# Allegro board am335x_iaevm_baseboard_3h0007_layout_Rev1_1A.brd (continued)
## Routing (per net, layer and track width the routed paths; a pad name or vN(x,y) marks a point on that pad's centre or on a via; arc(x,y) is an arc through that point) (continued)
GND_OSC0: length 14.5
  TOP w0.254: U2.V11 92.88,86.2 93.53,86.85 94.23,86.85 95.19,85.89 98.58,85.89 100.29,84.19 v1(100.29,83.02) ; C4.2 102.02,81.19 101.64,81.57 v1(101.64,81.83) 101.64,82.08 C5.2
  BOTTOM w0.254: v1(101.64,81.83) 101.13,82.33 101,82.33 C67.2 100.62,82.71 100.6,82.71 v1(100.29,83.02)
GND_OSC1: length 13.8
  TOP w0.102: U2.A5 77.94,81.14 77.1,81.14
  TOP w0.121: 77.1,81.14 76.22,81.14 75.24,80.16 71.56,80.16 71.31,79.92 67.56,79.92 C2.1 C3.1
GNDA_ADC: length 45.1
  TOP w0.305: v2(81,83.4) U2.E8
  TOP w0.508: v1(49.44,75.73) v1(57.19,75.73) ; v1(58.9,84.75) 59.66,84.75 59.92,84.49 v1(64.27,84.49) 64.53,84.75 R45.1
  BOTTOM w0.127: 79.56,82.99 79.79,83.22 79.79,83.6 80.05,83.86 80.54,83.86 v2(81,83.4)
  BOTTOM w0.152: 79.56,82.99 79.13,82.99 79.03,83.1 77.15,83.1
  BOTTOM w0.508: 77.15,83.1 76.94,83.1 75.99,82.14 FB10.1 75.09,83.25 73.9,84.44 71.16,84.44 70.66,84.94 66.83,84.94 66.38,84.49 v1(64.27,84.49) ; v1(57.19,75.73) 57.19,79.03 58.88,80.73 58.88,81.93 58.89,81.93 58.89,84.73 v1(58.9,84.75) ; C63.2 v1(49.44,75.73)
GNDA_TSC: length 60.2
  TOP w0.508: v1(43.29,80.4) 54.55,80.4 57.87,83.73 R45.2 65.19,83.48 R51.2 C13.2 C14.2 C11.2 C12.2 ; 49.82,57.31 J9.11
  BOTTOM w0.508: 49.82,57.31 50.96,57.31 51.45,57.8 51.45,64.45 49.62,66.28 47.76,66.28 42.18,71.87 42.18,79.29 v1(43.29,80.4)
GNDUSB0: length 26
  TOP w0.635: v1(124.62,168.26) 124.91,168.55 J14.S4 126.62,166.82 126.87,166.57 126.87,166 J14.S2 ; J14.S1 134.08,166 134.82,166.74 J14.S3 136.66,168.55 v1(136.94,168.26) FB14.2
  BOTTOM w0.635: v1(124.62,168.26) v1(136.94,168.26)
GNDUSB1: length 16.7
  TOP w0.635: FB19.2 154.6,165.66 J18.S1
  BOTTOM w0.635: J18.S1 151.94,168.31 139.98,168.31 J18.S2
V1_8D: length 35.1
  TOP w0.508: C133.1 v1(135.8,128.46) ; v1(133.01,50.52) 130.53,50.52 128.37,48.36 116.31,48.36 114.96,47.02 v1(113.56,47.02)
  LY4 w0.483: 132.75,87.13 J8.2 133.56,86.52
  LY4 w0.514: 135.8,123.46 J3.1 ; J3.1 134.89,124.37 ; J3.1 136.71,124.37 ; J3.1 135.8,125.28
  BOTTOM w0.508: C261.1 113.57,47.01 v1(113.56,47.02) R472.1 ; J8.2 132.63,86.65 C138.1 ; J3.1 v1(135.8,128.46)
V3_3D: length 210
  TOP w0.254: U32.6 v1(66.86,33.53)
  TOP w0.381: C140.1 50.08,65.7 49.82,65.44 49.82,63.66
  TOP w0.508: v1(75.09,146.34) 92.11,146.34 93.2,147.43 111.64,147.43 114.74,150.53 116.05,150.53 123.19,143.39 128.71,143.39 129.96,142.15 135.95,142.15 137.22,140.88 155.99,140.88 156.88,141.77 R386.2 ; v1(66.86,33.53) 66.86,32.84 67.09,32.61 C222.1
  TOP w0.635: v1(73.57,39.15) v1(71.03,39.15) v1(65.95,39.15) 58.97,39.15 58.52,38.7 ; 58.52,38.7 v1(46.97,38.7) ; 58.52,38.7 58.52,35.73 R544.2 58.77,33.69 59.62,32.84 66.86,32.84 ; v1(64.3,45.88) 63.09,44.68 59.03,44.68 57.82,45.88 50.33,45.88 v1(48.3,47.92)
  LY4 w0.514: 50.63,63.66 49.82,63.66 49.82,64.27 ; 48.17,136.16 J5.39 ; J5.39 49.08,137.07 ; J5.39 48.17,137.98 ; J5.39 47.26,137.07 ; 68.85,125.64 J6.15 ; J6.15 69.76,124.73 ; J6.15 70.67,125.64 ; J6.15 69.76,126.55
  BOTTOM w0.254: U27.6 65.59,46.03 C215.1
  BOTTOM w0.508: C135.1 v1(48.93,135.29) ; C134.1 69.76,124.24 J6.15
  BOTTOM w0.635: v1(46.97,38.7) v1(46.97,47.86) ; R454.2 v1(71.03,39.15) ; 73.57,40.42 v1(73.57,39.15) ; R455.2 v1(65.95,39.15) ; C215.1 v1(64.3,45.88)
  BOTTOM w0.762: R68.1 105.75,41.64 105.75,28.41 102.91,25.56 v1(102.91,22.26)
  vias: v1(113.45,24.55) v1(113.45,23.66) v1(113.45,22.77)
V5_0D: length 38.7
  TOP w0.121: U24.E2 U24.E1
  TOP w0.381: J7.2 J7.1
  TOP w0.508: v1(132.63,126.78) C132.1
  TOP w0.635: 136.05,146.79 U22.3 ; 136.05,146.79 134.78,146.79 U22.2 ; 136.05,146.79 143.1,146.79 ; C270.1 148.64,146.79 144.37,146.79 ; 143.1,146.79 U29.2 ; 143.1,146.79 144.37,146.79 ; 144.37,146.79 U29.3
  TOP w0.762: C137.1 139.23,88.05 137.71,86.52 J7.2
  LY4 w0.483: 135.93,87.13 J7.1 135.11,86.52 ; 138.01,86.52 J7.2 137.2,87.13
  LY4 w0.514: J3.2 133.26,125.28 ; J3.2 133.26,123.46 ; J3.2 132.35,124.37
  BOTTOM w0.381: 148.12,147.1 148.37,147.1
  BOTTOM w0.508: v1(132.63,126.78) 133.26,126.15 J3.2 ; 148.37,147.1 v1(149.52,148.25)
  BOTTOM w0.762: J7.1 134.66,86.52 C136.1
V5_0D_EN: length 1.6
  TOP w0.121: U24.A4 156.79,144.78 R386.1
VBAT: length 147.3
  TOP w0.121: U24.A1 U24.A2
  TOP w0.203: U4.6 89.25,29.68 89.16,29.6 v1(89.16,29.4) ; 93,31.49 U4.13 ; U4.3 88.05,30.18 88.02,30.15 88.02,29.85 87.67,29.5 v1(87.67,29.48) ; v1(90.53,37.63) 90.45,37.55 U4.28 ; v1(93.33,36) 93.07,35.75 93.07,35.7 92.87,35.49 U4.23 ; U4.36 87.25,37.01 87.11,37.15 ; U4.47 85.87,31.89 85.67,31.7 85.67,31.44 ; 85.51,34.29 U4.41
  TOP w0.381: v1(85.25,30.01) 85.25,30.02 85.25,31.03 85.67,31.44 ; R239.2 v1(126.91,79.79) ; v1(85.29,34.29) 85.51,34.29 ; 87.11,37.15 86.97,37.29 86.97,37.57 v1(86.91,37.63) ; v1(93.61,31.15) 93.34,31.15 93,31.49
  TOP w0.502: 77.23,10.2 SW1.2 ; SW1.2 79.06,10.2 ; SW1.2 78.14,11.11 ; SW1.2 78.14,9.28 ; 88.81,19.32 TP25.1 ; TP25.1 87.77,20.36 ; TP25.1 89.85,20.36 ; TP25.1 88.81,21.4
  TOP w0.762: J8.1 130.34,86.52 129.96,86.14 129.96,86.11 129.61,85.76 C139.1
  LY3 w1.016: v1(63.54,123.23) 34.45,123.23 33.95,122.72 v1(31.91,122.72)
  LY4 w0.483: 130.67,86.52 J8.1 131.48,87.13
  LY4 w0.514: 87.77,20.36 TP25.1 ; TP25.1 88.81,21.4 ; TP25.1 89.85,20.36 ; TP25.1 88.81,19.32 ; J19.2 124.65,59.92 ; J19.2 123.74,59 ; J19.2 122.82,59.92 ; J19.2 123.74,60.83 ; 77.23,10.2 SW1.2 ; SW1.2 78.14,9.28 ; SW1.2 78.14,11.11 ; SW1.2 79.06,10.2 ; J19.1 124.65,62.46 ; J19.1 123.74,61.54 ; J19.1 122.82,62.46 ; J19.1 123.74,63.37
  BOTTOM w0.381: C141.1 64.14,124.15 64.14,124.68
  BOTTOM w0.762: R80.2 6.26,87.41 6.39,87.29 ; R81.2 6.77,83.1 ; R82.2 6.77,78.65 ; R83.2 6.45,74.33
  BOTTOM w1.016: C253.1 v1(86.91,37.63) 86.91,37.76 86.38,38.28 C238.1 ; C240.1 92.38,31.15 v1(93.61,31.15) ; 6.45,74.33 6.77,74.65 6.77,86.91 6.39,87.29 6.39,95.03 11.85,100.49 v1(14.52,100.49) ; C252.1 88.72,30.32 89.16,29.88 v1(89.16,29.4) ; v1(31.91,101.51) v1(31.91,122.72) ; v1(93.33,36) 94.77,36 C251.1 ; C254.1 87.54,30.43 87.54,29.6 v1(87.67,29.48) ; C236.1 84.72,27.72 85.64,28.64 85.64,29.63 85.26,30.01 85.25,30.01 v1(85.25,30.01) ; C250.1 90.53,36.63 v1(90.53,37.63) ; J6.19 64.14,125.1 64.14,124.68 63.54,124.08 v1(63.54,123.23)
  vias: v1(83.48,20.36) v1(84.75,20.36) v1(85.76,20.36) v1(157.77,148.5) v1(158.53,148.5)
VBUS0_OTG_CAP: length 3.7
  TOP w0.635: J36.2 131.99,153.9 C182.1
VBUS1_OTG_CAP: length 6.6
  TOP w0.502: J37.2 154.53,158.75 ; J37.2 153.49,157.71 ; J37.2 154.53,156.67
  TOP w0.635: C185.1 J37.2
VDD1_SMPS: length 25.5
  TOP w0.254: U32.8 v1(67.79,35.15)
  TOP w0.635: R46.1 73.68,36.85 74.12,36.4 v1(74.91,36.4) ; v1(71.79,45.38) v1(71.79,44.74) 73.1,44.74 73.36,45 v1(75.54,45) 80.68,45
  LY3 w0.514: J19.6 124.65,49.76 ; J19.6 123.74,50.67 ; J19.6 123.74,48.84 ; J19.6 122.82,49.76
  BOTTOM w0.635: v1(74.91,36.4) 74.91,44.36 v1(75.54,45)
  vias: v1(81.06,45.38) v1(81.44,46.01) v1(81.83,45.38)
VDD2_SMPS: length 94.3
  BOTTOM w0.254: v1(70.01,46.93) 69.51,46.93 69.4,47.03 U27.8
  BOTTOM w1.016: J19.7 122.85,46.33 122.85,46.25 121.45,44.85 121.45,40.11 119.04,37.69 119.04,32.93 118.66,32.55 118.66,20.48 117.39,19.21 107.99,19.21 107.48,18.71 94.59,18.71 93.57,17.69 93.31,17.69 87.46,17.69 86.99,18.16 81.42,18.16 75.54,24.04 75.54,34.07 77.76,36.3 v1(77.76,38.26)
  vias: v1(70.52,48.42) v1(70.52,47.66) v1(76.62,38.26)
VDD3_SMPS: length 35.1
  TOP w0.508: v1(91.35,45.88) 92,45.88 R470.1 92.23,45.12 v1(91.35,45.12)
  TOP w0.635: J19.8 122.75,43.69 109.99,43.69 108.11,45.57 97.32,45.57 97.13,45.38 92.5,45.38 R470.1
VDD_CORE: length 62.6
  TOP w0.305: U2.J12 v2(84.2,87.4)
  TOP w0.381: U2.F6 v2(82.6,81.8) U2.G6 ; U2.L6 v2(85.8,81.8) U2.K6 ; v2(86.6,82.6) U2.L7 ; U2.N13 v2(87.4,88.2) U2.M13 ; v2(82.6,85.8) U2.G10 ; U2.N9 v2(88.2,84.2) U2.N8 ; U2.F7 v2(82.6,82.6) U2.G7 ; v2(86.6,83.4) U2.L8 v2(85.8,83.4) U2.K8 ; v2(87.4,86.6) U2.M11 ; v2(86.6,84.2) U2.L9 ; v2(88.2,87.4) U2.N12 ; U2.H11 v2(83.4,86.6) ; v2(85.8,87.4) U2.K12
  TOP w0.635: C17.1 v1(67.35,73.7)
  TOP w1.016: v1(67.35,73.7) v1(66.9,73.25) v1(66.46,72.81) 65.35,71.7 65.35,71.03 ; R32.2 70.54,45.78 71.16,46.39 73.32,46.39 ; C232.1 65.35,71.03 ; 65.35,71.03 65.19,70.86 65.19,69.86 62.01,66.69 62.01,61.24 64.99,58.26 65.26,58.26 v1(65.89,57.63) v1(66.46,57.06) v1(66.46,56.43)
  BOTTOM w0.381: v2(86.6,84.2) 86.14,84.66 C35.1 ; v2(82.6,85.8) 82.6,85.37 C19.1 ; C36.1 88.05,84.35 v2(88.2,84.2) ; v2(85.8,83.4) 85.65,83.4 85.19,83.86 C24.1 ; C34.1 85.5,87.1 v2(85.8,87.4)
  BOTTOM w0.635: 66.2,77 v1(65.06,77) ; C23.1 v1(70.14,72.94)
  BOTTOM w1.016: v1(65.89,57.63) v1(66.46,57.06) v1(66.46,56.43) 67.09,55.8 67.09,52.37 69.95,49.5 71.99,49.5 72.31,49.19 73.7,49.19 74.97,47.92 v1(74.97,46.65)
  vias: v1(73.57,46.65) v1(74.33,46.01)
VDD_MPU: length 77.9
  TOP w0.381: U2.F10 v2(81.8,85.8) U2.F11 U2.F12 v2(81.8,87.4) U2.F13 v2(82.6,88.2) U2.G13 83.06,87.8 83.18,87.92 83.62,87.92 83.74,87.8 U2.H13 v2(84.2,88.2) U2.J13
  TOP w0.635: v1(73.95,34.81) 73.85,34.71 73.19,34.71 72.68,34.2 R46.2
  LY3 w1.016: 64.93,81.83 64.92,81.81 61.64,81.81 60.92,81.09 60.92,80.02 63.49,77.46 63.49,69.86 64.86,68.49 65.44,68.49 66.2,67.73 v1(66.2,66.59) v1(66.2,65.95) v1(66.2,65.32)
  LY4 w1.016: v1(73.98,33.26) v1(73.98,34.05) 73.95,34.07 v1(73.95,34.81) 73.95,36.87 75.09,38.01 75.09,42.96 76.43,44.3 76.43,46.71 74.46,48.68 74.46,51.6 72.94,53.12 69.13,53.12 67.7,54.55 67.7,58.49 67.25,58.94 67.25,63.38 66.2,64.43 v1(66.2,65.32) v1(66.2,65.95) v1(66.2,66.59)
  BOTTOM w0.381: C83.1 84.42,87.98 v2(84.2,88.2) ; v2(81.8,87.4) 81.8,86.69 C41.1 ; v2(81.8,85.8) 81.8,85.15 C53.1
  BOTTOM w0.635: 69.38,81.7 70.01,82.33 v1(70.52,82.33) ; C56.1 71.41,81.57 v1(71.67,81.83) ; v1(65.32,80.81) 65.44,80.94 66.19,80.94 C246.1
VDD_RTC: length 6
  TOP w0.381: v2(80.2,81.8) U2.D6
  BOTTOM w0.203: 79.03,82.27 79.54,82.27 79.58,82.23 79.58,82.23 79.83,81.98 79.83,81.98 80.01,81.8 v2(80.2,81.8)
  BOTTOM w0.508: C65.1 76.58,80.81 76.89,81.13 76.91,81.13 78.05,82.27 79.03,82.27
VDDA1P8V_USB0: length 80
  TOP w0.381: v2(89.8,90.6) U2.R16 ; v2(88.2,90.6) U2.N16
  TOP w0.508: v1(95.54,131.89) 97.42,131.89 98.16,132.63 v1(116.62,132.63) ; C61.1 v1(115.86,136.94) 115.86,138.53 114.72,139.67 114.72,141.1 R502.2
  LY4 w0.381: v2(89.8,90.6) 89.24,91.16 88.75,91.16 88.2,90.61 v2(88.2,90.6)
  BOTTOM w0.508: v1(116.62,132.63) 116.62,136.18 v1(115.86,136.94) ; v1(95.54,131.89) 95.54,116.62 96.05,116.12 96.05,112.43 94.78,111.16 94.78,106.59 95.52,105.85 95.52,101.97 92.67,99.12 92.67,98.29 89.19,94.81 89.19,91.73 88.49,91.03 88.49,90.89 v2(88.2,90.6)
VDDA3P3V_USB0: length 76.1
  TOP w0.381: v2(89.8,89.8) U2.R15 ; v2(88.2,89.8) U2.N15
  TOP w0.508: R504.2 107.58,139.89 109.58,137.89 109.58,137.82 ; v1(108.88,104.66) 107.94,103.72 95.46,103.72 94.32,102.57 94.32,98.52 92.87,97.08 v1(92.87,96.56) ; 109.58,137.82 109.58,136.88 C62.1 ; 109.58,137.82 v1(109.59,137.81)
  LY3 w0.102: 91.2,91.48 91.32,91.35 ; v2(89.8,89.8) 89.79,89.8
  LY3 w0.127: 90.19,90.19 90.92,90.19 91.05,90.32 91.05,91.2 91.04,91.2 90.32,91.2 90.19,91.07 90.19,90.19 ; 90.19,90.19 90.18,90.18
  LY3 w0.254: 90.18,90.18 v2(89.8,89.8)
  LY3 w0.508: 91.05,91.2 91.2,91.35 91.2,94.98 92.78,96.56 v1(92.87,96.56)
  BOTTOM w0.102: 88.2,89.8 v2(88.2,89.8) 88.58,90.18 89.42,90.18 v2(89.8,89.8) 89.58,89.58 89.39,89.58 89.19,89.38 88.62,89.38 88.2,89.8
  BOTTOM w0.508: v1(108.88,104.66) 108.88,137.1 v1(109.59,137.81)
VDDA_ADC: length 157.6
  TOP w0.121: 124.62,160.69 124.62,160.69 124.74,160.57 124.75,160.57
  TOP w0.508: R30.1 65.64,88.5 65.64,88.34 65.63,88.34 v1(65.63,86.91) 65.32,86.59 58.07,86.59 v1(58.01,86.65) ; v1(53.76,78.78) 48.3,78.78 v1(47.92,78.4) ; Q5.S 125.82,160.01 R565.2 124.75,160.57 v1(124.37,160.95)
  LY3 w0.508: v1(112.25,108.85) 108.9,112.2 98.59,112.2 98.26,111.88 91.12,111.88 89.79,110.55 77.89,110.55 77.45,110.12 76.14,110.12 v1(73.49,107.48)
  LY4 w0.508: v1(65.63,86.91) 65.67,86.91 68.11,89.34 70.32,89.34 71.41,90.44 71.41,93.14 72.81,94.53 72.81,106.79 v1(73.49,107.48)
  BOTTOM w0.508: v1(58.01,86.65) 58.01,85.93 58.25,85.69 58.25,82.2 58.25,82.19 58.25,81.11 55.92,78.78 v1(53.76,78.78) 53.7,78.72 FB9.1 ; v1(124.37,160.95) 123.1,159.68 123.1,156.5 122.08,155.49 122.08,146.6 120.79,145.3 120.79,135.89 115.56,130.66 115.56,128.51 114.03,126.99 114.03,125.69 112.25,123.91 v1(112.25,108.85) ; v1(47.92,78.4) R501.2
VDDMPU_MON: length 4.8
  TOP w0.381: U2.A2 77.48,79 76.87,78.4 73.82,78.4 R561.1
VDDS_DDR: length 94.4
  TOP w0.305: v1(95.8,67.79) 95.22,67.22 95.03,67.22
  TOP w0.381: v1(97.96,56.64) U31.C9 ; v1(75.74,63.84) U8.C1 ; v1(73.34,63.84) U8.E1 ; v1(97.96,63.84) U31.C1 ; U8.C7 75.67,58.3 75.67,58.27 v1(75.73,58.2) ; v1(73.34,56.64) U8.E9 ; v1(75.74,56.64) U8.C9 ; v1(97.96,61.44) U31.C3 ; v1(99.56,56.64) U31.A9 ; v1(70.94,56.64) U8.H9 ; v1(77.33,63.84) U8.A1 ; v1(95.56,63.84) U31.E1 ; v1(93.16,56.64) U31.H9 ; v1(77.33,56.64) U8.A9 ; v1(90.76,63.84) U31.L1 ; v1(68.54,63.84) U8.L1 ; v1(95.56,56.64) U31.E9 ; v1(99.56,63.84) U31.A1 ; v1(75.74,61.44) U8.C3 ; v1(97.96,58.24) U31.C7
  TOP w0.508: v1(67.6,68.62) 67.6,69.51 67.86,69.76 C266.1 68.76,68.7 v1(68.62,68.55)
  TOP w0.635: R508.1 107.61,69.44 107.35,69.19 v1(105.6,69.19) v1(104.76,69.19) ; v1(103.8,38.96) 120.56,38.96 J19.9 ; R467.1 103.8,28.37 v1(103.8,29.37) v1(103.8,30.64)
  BOTTOM w0.254: v1(77.33,56.64) 76.87,56.17 C155.1 ; v1(97.96,58.24) 97.83,58.37 C195.1
  BOTTOM w0.305: C125.1 69,68.17 v1(68.62,68.55)
  BOTTOM w0.381: v1(73.34,56.64) 73.13,56.43 C126.1 ; 70.9,55.79 70.94,55.82 v1(70.94,56.64) ; C218.1 68.62,63.92 v1(68.54,63.84) ; v1(90.76,63.84) 90.84,63.92 C188.1 ; v1(93.16,56.64) 93.16,55.82 C174.1 ; C221.1 75.6,61.3 v1(75.74,61.44) ; C216.1 99.48,63.92 v1(99.56,63.84) ; v1(95.56,63.84) 95.65,63.84 96.3,64.49 C202.1 ; v1(99.56,56.64) 99.73,56.46 C181.1 ; C156.1 97.83,61.3 v1(97.96,61.44) ; C266.1 v1(67.6,68.62) ; v1(73.34,63.84) 73.55,63.84 74.08,64.36 C219.1 ; C217.1 77.25,63.92 v1(77.33,63.84) ; v1(97.57,54.8) C189.1 97.95,56.17 97.95,56.63 v1(97.96,56.64)
  BOTTOM w0.635: v1(99.1,55.03) v1(99.73,55.03) 99.73,50.9 98.4,49.57 98.4,47.28 103.8,41.88 v1(103.8,38.96) v1(103.8,30.64) v1(103.8,29.37)
VDDS_OSC: length 47.5
  TOP w0.305: U2.R11 v2(89.8,86.6)
  LY4 w0.508: v1(93.79,85.53) 93.51,85.25 93.51,84 94.66,82.84 96.17,82.84 97.31,83.98 100.49,83.98 101,83.48 101,81.44 101.38,81.06 v1(102.97,81.06)
  BOTTOM w0.381: v2(89.8,86.6) 90.87,85.53 v1(93.79,85.53)
  BOTTOM w0.508: R506.1 113.54,65 110.72,65 109.83,65.89 109.83,77.57 106.34,81.06 v1(102.97,81.06) 101.26,81.06 C67.1
VDDS_PLL_CORE_LCD: length 36.1
  TOP w0.102: U2.R10 89.41,85.4
  TOP w0.381: 89.41,85.4 v2(89.8,85.01)
  LY4 w0.508: v1(99.35,81.89) 98.26,81.89 97.94,82.21 94.4,82.21 91.02,85.58 90.36,85.58 90.02,85.24 90.02,85.23 v2(89.8,85.01)
  BOTTOM w0.508: v1(99.35,81.89) 99.67,81.57 99.68,81.57 100.05,81.2 100.05,81.13 100.75,80.43 105.45,80.43 107.51,78.37 107.51,66.42 107.48,66.39 C64.1 107.51,65.67 R503.1
VDDS_PLL_DDR: length 44.2
  TOP w0.381: U2.E7 v2(81,82.6)
  LY3 w0.102: v2(81,82.6) 80.99,82.6 80.61,82.98 79.93,82.98 79.54,82.59 79.92,82.21 80.62,82.21 81,82.59 v2(81,82.6)
  LY3 w0.508: 79.54,82.59 78.65,82.59 75.41,79.35 68.81,79.35 v1(68.24,78.78)
  BOTTOM w0.508: v1(68.24,78.78) 68.24,75.08 68.3,75.02 68.3,73.12 65.7,70.52 65.7,69.51 62.9,66.71 C73.1 62.9,59.16 59.95,56.2 R507.2
VDDS_PLL_MPU: length 46.8
  TOP w0.102: U2.H15 v2(83.4,89.8)
  TOP w0.508: R497.2 94.24,115.86 v1(94.24,117)
  LY3 w0.508: v1(81.93,111.39) 89.73,111.39 91.03,112.69 v1(94.27,112.69)
  LY4 w0.102: 82.18,90.21 82.18,89.6 82.4,89.38 82.97,89.38 83.39,89.8 v2(83.4,89.8) 83.4,89.84 83,90.24 ; 82.18,90.21 82.18,90.72 82.49,91.03 83,91.03 83,90.24 ; 82.18,90.21 82.97,90.21 83,90.24
  LY4 w0.508: v1(81.93,111.39) 81.44,110.91 81.44,104.81 80.96,104.32 80.96,100 81.28,99.68 81.28,98.49 80.85,98.06 80.85,93.71 83,91.56 83,91.03
  BOTTOM w0.508: v1(94.27,112.69) C70.1 94.27,114.34 94.24,114.37 v1(94.24,117)
VDDS_RTC: length 37.2
  TOP w0.305: v2(80.2,82.6) U2.D7
  BOTTOM w0.508: v1(70.52,81.5) 70.07,81.05 70.07,80.74 68.94,79.61 68.94,72.62 66.33,70.01 66.33,68.24 65.12,67.03 C66.1 64.43,58.58 64.43,57.06 64.94,56.55 64.94,52.43 64.68,52.17 64.68,50.14 63.85,49.31 R505.1
VDDS_SRAM_CORE_BG: length 49.3
  TOP w0.381: v2(81,84.2) U2.E9
  TOP w0.508: v1(50.2,102.53) 50.33,102.65 66.51,102.65 v1(66.56,102.7)
  BOTTOM w0.102: 78.84,84.62 79.86,84.62 80.28,84.2 v2(81,84.2)
  BOTTOM w0.508: R500.2 49.11,102.75 49.97,102.75 v1(50.2,102.53) 50.33,102.4 51.09,102.4 ; v1(66.56,102.7) 66.56,93.59 67.18,92.96 67.18,90.23 68.92,88.5 71.26,88.5 72.05,87.71 72.05,87.16 73.51,85.7 74.53,85.7 75.86,84.37 78.59,84.37 78.84,84.62
VDDS_SRAM_MPU_BB: length 60.8
  TOP w0.381: v2(80.2,85.8) U2.D10
  TOP w0.508: v1(51.93,107.4) 57.97,107.4 58.84,106.54 66.36,106.54 v1(67.22,107.4)
  BOTTOM w0.381: 79.59,86.38 79.96,86.02 79.98,86.02 v2(80.2,85.8)
  BOTTOM w0.508: v1(51.93,107.4) 51.93,98.92 C69.1 ; 79.59,86.38 77.41,86.38 76.82,86.97 74.56,86.97 74.56,86.97 74.03,86.97 74.03,86.97 73.25,86.97 72.68,87.54 72.68,87.98 71.52,89.14 69.62,89.14 67.96,90.8 67.96,93.79 67.3,94.45 67.3,104.08 67.65,104.43 67.65,106.97 v1(67.22,107.4)
  BOTTOM w0.635: C69.1 50.2,97.95 v1(50.08,98.08) 49.28,98.08 R499.2
VDDSHV1: length 185.8
  TOP w0.305: U9.37 148.76,117.38 v1(148.5,117.64) ; U9.34 v1(150.26,117.66) ; v1(148.37,98.08) 148.75,97.7 U9.12 ; U9.39 147.76,117.44 v1(147.53,117.66)
  TOP w0.635: v1(153.45,95.64) 153.45,94.3 152.64,93.48 148.86,93.48 148.5,93.84 C128.1 148.5,95.16 v1(148.37,95.29) ; v1(147.53,117.66) 147.53,118.45 C131.1 C130.1 150.48,118.45 150.48,117.89 v1(150.26,117.66) ; v1(148.37,98.08) 148.37,98.31 147.76,98.92 145.66,98.92 v1(145.57,98.82)
  LY3 w0.635: v1(153.45,95.64) 151.68,93.86 151.68,88.18 150.95,87.45 150.95,73.35 147.29,69.7 118.21,69.7 v1(117.89,69.38)
  LY4 w0.508: v1(54.82,86.37) 56.65,86.37 57.44,85.58 59.5,85.58 65.36,79.72 75.14,79.72 79.44,75.42 84.52,75.42 87.36,72.58 93.61,72.58 94.9,71.29 115.98,71.29 v1(117.89,69.38)
  BOTTOM w0.508: FB2.1 54.33,85.57 54.82,86.07 v1(54.82,86.37)
  BOTTOM w0.635: R493.2 119.39,69.38 v1(117.89,69.38) ; C129.1 v1(148.5,117.64) ; v1(148.37,95.29) 148.5,95.41 C127.1 148.5,97.95 v1(148.37,98.08) ; R130.2 v1(153.45,95.64)
  BOTTOM w0.762: FB2.1 FB1.1 ; v1(148.5,117.64) 148.47,117.66 v1(147.53,117.66) 146.65,116.78 146.65,105.32 146.52,105.19 146.52,100.27 145.91,99.66 145.91,99.17 v1(145.57,98.82) 145.43,98.68 145.43,97.34 R131.2 145.58,96.56 146.09,96.05
VDDSHV2: length 71.3
  TOP w0.635: v1(77.46,117.89) 77.63,117.72 88.89,117.72 92.01,120.84 103.71,120.84 104.05,120.49 104.98,120.49 v1(105.04,120.43) ; v1(105.75,100.95) 106.15,100.55 v1(111.99,100.55)
  BOTTOM w0.635: v1(105.75,100.95) 105.66,101.05 105.66,107.98 104.37,109.27 104.37,113.19 105.57,114.4 105.57,119.91 105.06,120.43 v1(105.04,120.43) ; R545.2 111.64,96.71 FB5.1 v1(111.99,100.55) ; J6.11 C148.1 75.37,123.86 75.75,123.48 75.75,120.69 77.46,118.99 v1(77.46,117.89)
VDDSHV3: length 10
  TOP w0.635: R546.2 132.27,136.69 128.69,136.69 127.86,137.51 FB21.1 FB20.1
VDDSHV4: length 55.8
  TOP w0.254: U19.10 v1(56.87,144.06)
  TOP w0.381: U20.10 v1(71.92,148.12)
  TOP w0.508: C255.1 v1(54.1,145.03) ; J13.4 53.87,147.18 54.08,146.98 v1(54.27,146.98) 54.46,146.98 54.73,147.24 J13.19
  TOP w0.635: v1(115.35,149.77) 115.73,149.77 122.97,142.53 127.87,142.53 128.12,142.28 v1(128.12,142.28)
  BOTTOM w0.635: R373.2 R372.2 56.55,166.28 55.66,165.39 v1(55.66,164.38) ; v1(46.14,164.38) 46.14,165.9 46.52,166.28 R370.2 R371.2 ; R494.2 134.37,130.97 133.13,130.97 131.61,132.5 130.91,132.5 FB4.1 130.4,134.85 128.12,137.13 v1(128.12,142.28) ; v1(54.27,146.98) 53.76,147.48 C180.1 ; R369.2 v1(43.09,148.88) ; R367.2 R368.2 R366.2 48.55,149.52 v1(48.17,149.9) ; R365.2 46.39,149.52 v1(46.01,149.9)
VDDSHV5: length 118.3
  LY3 w0.762: v1(103.06,139.74) 109.77,139.74 111.42,138.09 v1(114.59,138.09) ; v1(130.4,128.46) 127.74,128.46 127,129.2 126.37,129.2 126.12,129.45 114.72,129.45 v1(114.59,129.32)
  LY4 w0.762: v1(114.53,58.39) 114.59,58.46 116.75,58.46 117.89,59.6 117.89,63.92 117.75,64.06 117.75,67.41 119.06,68.72 119.06,82.08 115.61,85.53 115.61,93.13 114.59,94.14 v1(114.59,129.32) v1(114.59,138.09)
  BOTTOM w0.635: FB6.1 v1(114.53,58.39)
  BOTTOM w0.762: R495.2 v1(103.06,139.74) ; FB3.1 v1(130.4,128.46)
VDDSHV6: length 169.4
  TOP w0.381: v1(77.99,99) 77.7,99.28 77.7,100.05 77.89,100.23 77.89,100.76 77.7,100.94 v1(77.7,102.45) ; U7.8 v1(138.4,69) ; R378.2 63.29,145.06 U21.1
  TOP w0.635: R382.1 v1(138.98,151.99) 138.95,151.99 138.71,152.24 138.71,154.64 139.42,155.36 144.31,155.36 145.33,156.37 v1(145.33,157.14) ; R378.2 v1(63.16,145.96) ; v1(25.18,80.87) 39.92,80.87 40.29,81.25 52.23,81.25 52.23,81.25 v1(52.93,81.25) ; v1(146.09,157.2) 146.09,156.18 146.91,155.36 R412.1 ; J2.5 v1(22.01,94.27)
  LY3 w0.381: v1(54.9,98.08) 55.16,97.83 69.63,97.83 v1(70.65,98.84) 71,99.2 74.46,99.2 74.99,99.73 77.51,99.73 77.99,99.25 v1(77.99,99)
  BOTTOM w0.381: v1(138.4,69) 138.59,69 C116.1 v1(139.74,68.87) R72.2 ; R548.2 R547.2 78.52,98.46 v1(77.99,99) ; v1(77.7,102.45) 77.7,102.35 77.76,102.3 R554.2 R555.2 ; R559.2 v1(10.83,49.31) ; R552.2 R553.2 71.03,98.15 70.65,98.53 v1(70.65,98.84)
  BOTTOM w0.508: v1(165.82,56.43) R101.2 R100.2 ; v1(165.82,51.35) R103.2 R102.2 ; R106.2 R107.2 v1(165.9,84.11) ; R104.2 R105.2 v1(165.82,89.19) ; R96.2 R97.2 v1(165.82,66.59) ; v1(165.82,61.51) R99.2 R98.2 ; R110.2 R111.2 165.77,73.95 v1(165.82,73.9) ; R108.2 R109.2 165.76,79.03 v1(165.82,78.96)
  BOTTOM w0.635: v1(54.9,98.08) 54.43,97.61 54.43,95.45 53.25,94.27 FB7.1 FB8.1 54.58,90.65 54.58,88.14 54.11,87.67 53.72,87.67 R496.2 52.93,86.88 v1(52.93,81.25) ; 25.18,89.19 R6.2 v1(25.18,80.87) 25.18,69.38 21.37,65.57 v1(21.37,64.93) ; 25.18,89.19 25.74,89.19 v1(25.87,89.32) ; 25.18,89.19 R71.2 ; C115.1 v1(22.01,94.27) ; R70.2 29.21,89.02 28.22,89.02 v1(27.49,88.3)
AM335X_AIN0: length 67.2
  TOP w0.102: U2.B6 79,82.24 78.65,82.59 77.1,82.59
  TOP w0.121: 77.1,82.59 77.07,82.62 73.1,82.62 72.62,83.1 70.4,83.1 69.76,82.46 68.87,82.46 68.64,82.23 65.94,82.23 65.62,81.9 64.67,81.9 64.57,82.01 60.47,82.01 60.25,82.23 58.4,82.23 55.46,79.29 48.04,79.29 47.03,78.27 41.69,78.27 41.03,77.61 v1(40.9,77.61)
  BOTTOM w0.095: 47.79,56.68 49.19,56.68 49.82,56.04
  BOTTOM w0.121: v1(40.9,77.61) 40.9,71.42 47.1,65.21 47.1,57.19 47.61,56.68 47.79,56.68
AM335X_AIN1: length 77.1
  TOP w0.102: v2(79.4,83.4) U2.C7
  TOP w0.121: v1(64.93,85.69) 58.1,85.69 55.94,87.84 44.72,87.84 43.42,86.55 v1(43.42,85.53)
  BOTTOM w0.095: 47.79,55.41 49.19,55.41 49.82,54.77
  BOTTOM w0.102: v2(79.4,83.4) 78.92,83.4 78.84,83.48 77.79,83.48 77.73,83.54 77.1,83.54
  BOTTOM w0.121: 77.1,83.54 75.67,83.54 74.21,85 71.54,85 71.16,85.38 65.82,85.38 65.75,85.31 65.31,85.31 v1(64.93,85.69) ; v1(43.42,85.53) 43.11,85.22 43.11,82.78 40.4,80.08 40.4,79.26 40.21,79.07 40.21,71.14 46.19,65.16 46.19,56.7 47.48,55.41 47.79,55.41
AM335X_AIN2: length 74.8
  TOP w0.102: 77.1,83.41 78.59,83.41 79,83 U2.B7
  TOP w0.121: 77.1,83.41 76.55,83.41 76.08,83.89 75.19,83.89 74.21,84.87 70.52,84.87 70.4,84.75 70.4,84.37 69.95,83.92 69.13,83.92 67.93,82.72 66.14,82.72 65.7,82.72 65.38,82.4 64.88,82.4 64.77,82.51 60.87,82.51 60.65,82.72 57.75,82.72 54.81,79.78 47.55,79.78 46.8,79.02 40.78,79.02 40.19,79.62 v1(39.71,79.62)
  BOTTOM w0.095: 47.91,54.14 49.18,54.14 49.82,53.5
  BOTTOM w0.121: v1(39.71,79.62) 39.71,70.52 45.38,64.86 45.38,55.76 47,54.14 47.91,54.14
AM335X_AIN3: length 73.2
  TOP w0.102: U2.A7 77.1,83
  TOP w0.121: 77.1,83 76.78,83 76.65,82.87 73.2,82.87 72.47,83.6 69.16,83.6 68.17,82.62 68.03,82.47 66.04,82.47 66.04,82.48 65.84,82.48 65.51,82.15 64.78,82.15 64.67,82.26 60.74,82.26 60.53,82.47 57.99,82.47 55.05,79.53 47.66,79.53 46.8,78.68 v1(39.27,78.68)
  BOTTOM w0.095: 49.82,52.23 49.19,52.87 47.79,52.87
  BOTTOM w0.121: 47.79,52.87 44.79,55.87 44.79,65.01 39.27,70.53 v1(39.27,78.68)
AM335X_AIN4: length 72.1
  TOP w0.102: U2.C8 79.42,84.18 v2(79.38,84.18)
  TOP w0.121: v1(43.62,83.2) 47.27,86.84 56.54,86.84 58.13,85.25 65.18,85.25 65.57,85.64 v1(65.57,85.76)
  BOTTOM w0.121: v1(43.62,83.2) 43.62,82.51 40.65,79.54 40.65,78.98 40.45,78.78 40.45,71.4 46.54,65.32 46.54,57.11 47.61,56.04 J9.13 ; v2(79.38,84.18) 78.99,84.18 78.6,83.79 75.79,83.79 74.33,85.25 71.67,85.25 71.29,85.63 66.27,85.63 66.14,85.76 v1(65.57,85.76)
AM335X_AIN5: length 77.7
  TOP w0.102: U2.B8 78.71,83.8 78.38,84.13 77.1,84.13
  TOP w0.121: v1(72.43,85.76) 72.8,85.39 74.41,85.39 75.42,84.38 76.29,84.38 76.54,84.13 77.1,84.13 ; v1(42.84,88.53) 43.28,88.53 43.47,88.34 58.55,88.34 59.22,87.67 64.21,87.67 v1(64.68,88.13)
  BOTTOM w0.121: v1(64.68,88.13) 65.08,87.74 67.26,87.74 67.37,87.62 67.39,87.62 69.13,85.89 71.86,85.89 71.99,85.76 v1(72.43,85.76) ; v1(42.84,88.53) 42.84,83.04 40.15,80.36 40.15,79.43 39.96,79.24 39.96,70.83 45.86,64.93 45.86,56.25 47.33,54.77 J9.15
AM335X_AIN6: length 60.1
  TOP w0.095: 49.19,54.14 50.58,54.14 50.71,54.01
  TOP w0.102: 77.1,83.8 U2.A8
  TOP w0.121: 50.71,54.01 51.73,53 51.73,52.11 52.39,51.45 v1(58.38,51.45) ; v1(68.11,83.86) 68.42,84.17 69.82,84.17 70.14,84.49 70.14,84.87 70.39,85.12 74.33,85.12 75.31,84.13 76.18,84.13 76.52,83.8 77.1,83.8 ; 49.19,54.14 J9.17
  BOTTOM w0.121: v1(68.11,83.86) 67.61,83.36 67.61,75.08 67.86,74.84 67.86,74.46 67.6,74.2 67.03,74.2 65.96,73.12 65.96,72.42 65.19,71.65 65.19,69.89 62.08,66.78 62.08,59.54 58.38,55.84 v1(58.38,51.45)
AM335X_AIN7: length 208.4
  TOP w0.102: v2(79.4,85) U2.C9
  TOP w0.121: v1(118.2,153.99) 116.93,152.72 108.95,152.72 107.99,151.75 95.74,151.75 95.25,151.26 v1(83.46,151.26) ; R571.2 v1(129.45,160.13) 129.48,160.13 R23.1 ; v1(75.81,85.32) 75.81,85.89 75.43,86.27 75.03,86.27 74.52,86.78 72.05,86.78 71.68,86.41 71.68,86.41 71.67,86.4 68.49,86.4 67.85,87.04 67.85,89.4 67.56,89.7 67.14,89.7 67.01,89.57 66.67,89.57 66.54,89.7 66.12,89.7 65.87,89.44 65.86,89.44 65.63,89.21 65.46,89.21 65.19,88.94 65.19,88.31 65.19,88.3 65.19,88.02 64.2,87.03 59.03,87.03 57.97,88.09 44.27,88.09 42.38,86.2 v1(42.38,85.76)
  LY3 w0.133: v1(118.2,153.99) 123.3,153.99 v1(129.45,160.13)
  LY4 w0.102: 77.1,87.3 v2(79.4,85)
  LY4 w0.133: 77.1,87.3 74.4,90 74.4,91.38 74.14,91.63 74.14,102.41 76.04,104.31 76.04,114.63 80.89,119.47 80.89,134.33 82.49,135.93 82.49,145.35 82.32,145.52 82.32,150.11 v1(83.46,151.26)
  BOTTOM w0.102: 77.84,84.95 77.84,84.96 78.61,84.96 78.67,85.03 79.01,85.03 79.03,85 v2(79.4,85)
  BOTTOM w0.121: v1(75.81,85.32) 76.17,84.95 77.84,84.95 ; v1(42.38,85.76) 42.38,83.07 38.83,79.52 38.83,70.41 44.36,64.88 44.36,55.58 47.7,52.23 J9.19
AM335X_DDR_A0: length 9.4
  TOP w0.102: U2.F3 v2(81.8,79.4)
  BOTTOM w0.102: v2(81.8,79.4) 81.8,79.09 80.11,77.4
  BOTTOM w0.121: R18.1 78.1,73.21 78.1,76.15 78.5,76.55 79.25,76.55 80.11,77.4
AM335X_DDR_A1: length 6
  TOP w0.102: U2.H1 83.8,77.4
  TOP w0.121: 83.8,77.4 83.8,76.83 83.8,76.62 83.67,76.49 83.22,76.49 83.1,76.36 83.1,75.67 83.54,75.22 83.54,73.51 83.16,73.13 R21.1
AM335X_DDR_A2: length 10.5
  TOP w0.102: U2.E4 v2(81,80.2)
  BOTTOM w0.102: v2(81,80.2) 81,79.94 81.38,79.56 81.38,79.22 79.56,77.4
  BOTTOM w0.121: 79.56,77.4 78.96,76.81 78.39,76.81 77.86,76.27 77.86,73.92 R31.1
AM335X_DDR_A3: length 7.7
  TOP w0.102: v2(79.4,79.4) U2.C3
  BOTTOM w0.102: 77.33,79.87 78.93,79.87 v2(79.4,79.4)
  BOTTOM w0.121: 77.33,79.87 77.19,79.73 77.19,78.98 76.93,78.72 76.56,78.72 75.87,79.41 75.15,79.41 R33.1
AM335X_DDR_A4: length 8.4
  TOP w0.102: 79.85,78.95 80.13,78.67 80.13,77.91 79.62,77.4
  TOP w0.121: R34.1 76.75,74.15 77.07,74.15 77.81,74.89 77.81,75.22 79.22,76.63 79.22,77 79.62,77.4 ; U2.C2 79.85,78.95
AM335X_DDR_A5: length 7.3
  TOP w0.102: 78.98,77.94 79,77.97 U2.B1
  TOP w0.121: 78.98,77.94 78.68,77.65 78.67,77.65 78.26,77.25 75.37,77.25 74.19,76.06 74.19,75.97 73.19,74.97
AM335X_DDR_A6: length 13.3
  TOP w0.305: v2(80.2,81) U2.D5
  BOTTOM w0.102: v2(80.2,81) 80.2,80.97 80.62,80.56 80.62,79.22 79.09,77.7 77.1,77.7
  BOTTOM w0.121: R36.1 74.78,76.68 75.79,77.7 77.1,77.7
AM335X_DDR_A7: length 7.6
  TOP w0.102: U2.E2 81.41,79 81.78,78.63 81.78,77.76 81.57,77.55
  TOP w0.121: R37.1 79.29,75.15 80.43,76.3 80.43,76.68 80.56,76.81 81.44,76.81 81.57,76.94 81.57,77.55
AM335X_DDR_A8: length 9.7
  TOP w0.102: v1(80.2,80.2) U2.D4
  BOTTOM w0.102: 77.1,78.54 78.13,79.56 78.7,79.56 79.24,79.02 80.07,79.02 80.2,79.15 v1(80.2,80.2)
  BOTTOM w0.121: R38.1 74.65,77.44 75.68,78.47 77.03,78.47 77.1,78.54
AM335X_DDR_A9: length 8
  TOP w0.121: R39.1 76.08,74.43 76.95,74.43 77.53,75.02 77.53,75.29 78.97,76.73 78.97,77.1 79.8,77.93 U2.C1
AM335X_DDR_A10: length 10.2
  TOP w0.102: U2.F4 v2(81.8,80.2)
  BOTTOM w0.102: 80.51,77.4 82.21,79.09 82.21,79.79 81.8,80.2 v2(81.8,80.2)
  BOTTOM w0.121: 80.51,77.4 80.46,77.4 79.36,76.3 78.84,76.3 78.4,75.86 78.4,73.19 R40.1
AM335X_DDR_A11: length 7
  TOP w0.102: 82.22,77.27 82.58,77.63 82.58,78.66 82.24,79 U2.F2
  TOP w0.121: 82.22,77.27 82.22,76.76 81.63,76.17 81.63,75.79 81.51,75.67 81.31,75.67 81,75.35 81,74.07 81.06,74.01 81.06,73.64 81,73.58 81,73.32 R41.1
AM335X_DDR_A12: length 9.8
  TOP w0.102: v2(81,79.4) U2.E3
  BOTTOM w0.102: v2(81,79.4) 81,79.29
  BOTTOM w0.121: R42.1 77.6,74.62 77.6,76.52 78.14,77.06 78.81,77.06 81,79.25 81,79.29
AM335X_DDR_A13: length 5.2
  TOP w0.102: U2.H3 v2(83.4,79.4)
  BOTTOM w0.102: 81.9,77.4 83.4,78.9 v2(83.4,79.4)
  BOTTOM w0.121: R43.1 81.19,76.69 81.9,77.4
AM335X_DDR_A14: length 5.9
  TOP w0.102: v2(83.4,80.2) U2.H4
  BOTTOM w0.102: 82.54,77.4 83.79,78.65 83.79,79.79 83.4,80.19 v2(83.4,80.2)
  BOTTOM w0.121: R44.1 82.14,77 82.54,77.4
AM335X_DDR_BA0: length 6.3
  TOP w0.102: U2.C4 v1(79.4,80.2)
  BOTTOM w0.102: v1(79.4,80.2) 77.29,80.2 77.2,80.1
  BOTTOM w0.121: 77.2,80.1 76.94,79.85 76.46,79.85 76.27,79.65 74.45,79.65 R47.1
AM335X_DDR_BA1: length 6.5
  TOP w0.102: U2.E1 81.4,77.78 80.68,77.06 80.45,77.06 80.18,76.78 80.18,76.67
  TOP w0.121: R49.1 78.33,74.08 78.93,74.67 78.93,75.14 79.04,75.26 80.18,76.4 80.18,76.67
AM335X_DDR_BA2: length 7.7
  TOP w0.102: U2.B3 79,79.52 78.59,79.11 78.59,77.99 78.09,77.49 77.1,77.49
  TOP w0.121: R549.1 74.11,77.13 74.48,77.49 77.1,77.49
AM335X_DDR_CASN: length 6.4
  TOP w0.102: 81.84,77.4 82.2,77.76 U2.F1
  TOP w0.121: 81.84,77.4 81.84,76.73 81.67,76.55 80.81,76.55 80.68,76.43 80.68,75.98 80.17,75.48 80.17,73.19 R13.1
AM335X_DDR_CKE: length 5.7
  TOP w0.102: U2.G3 v2(82.6,79.4)
  BOTTOM w0.102: v2(82.6,79.4) 82.6,79.03 80.97,77.4
  BOTTOM w0.121: 80.97,77.4 80.87,77.3 80.87,77.25 R537.1
AM335X_DDR_CLK: length 8
  TOP w0.095: U2.D2 80.9,79 81,78.9 81,78.03 80.89,77.92 80.89,77.81 79.92,76.85 79.92,76.54 78.5,75.12 78.5,74.75 77.38,73.63 R11.1
AM335X_DDR_CLKN: length 7.1
  TOP w0.095: R12.1 77.1,73.54 77.1,73.75 78.22,74.87 78.22,75.24 79.64,76.66 79.64,76.97 80.6,77.93 U2.D1
AM335X_DDR_CSN: length 6.6
  TOP w0.102: 84.32,77.04 84.32,77.42 84.17,77.57 84.17,78.65 83.82,79 U2.H2
  TOP w0.121: 84.32,77.04 84.32,76.55 84.19,76.43 84.17,76.43 84.05,76.3 84.05,75.67 84.56,75.16 84.56,73.63 R538.1
AM335X_DDR_D0: length 6.7
  TOP w0.102: v2(87.4,79.4) U2.M3
  BOTTOM w0.102: 87.4,77.4 v2(87.4,79.4)
  BOTTOM w0.121: R429.1 87.72,73.65 87.72,76.39 87.4,76.71 87.4,77.4
AM335X_DDR_D1: length 9
  TOP w0.102: v2(87.4,80.2) U2.M4
  BOTTOM w0.102: v2(87.4,80.2) 87.4,80.19 87.79,79.79 87.79,77.63 88.03,77.4
  BOTTOM w0.121: R522.1 88.94,74.33 89.83,75.22 89.83,76.14 89.1,76.87 88.56,76.87 88.03,77.4
AM335X_DDR_D2: length 7.7
  TOP w0.102: U2.N1 87.8,77.56 87.96,77.4
  TOP w0.121: 87.96,77.4 88.25,77.11 89.18,77.11 89.64,76.65 90.1,76.65 90.62,76.14 90.92,76.14 91.6,75.45 91.6,73.76 91.67,73.7 R523.1
AM335X_DDR_D3: length 9.1
  TOP w0.102: U2.N2 87.8,78.74 88.26,78.28 ; 88.26,78.06 88.26,77.86 88.72,77.4
  TOP w0.121: 88.72,77.4 88.76,77.36 89.28,77.36 89.74,76.9 90.21,76.9 90.64,76.47 91.78,76.47 91.91,76.34 91.91,73.84 R524.1 ; 88.26,78.06 88.26,78.28
AM335X_DDR_D4: length 8.1
  TOP w0.102: U2.N3 v2(88.2,79.4)
  BOTTOM w0.102: 88.98,77.4 88.2,78.18 v2(88.2,79.4)
  BOTTOM w0.121: R525.1 90.71,73.45 90.71,74.13 90.08,74.77 90.08,76.3 88.98,77.4
AM335X_DDR_D5: length 5.7
  TOP w0.102: U2.N4 v2(88.2,80.2)
  BOTTOM w0.102: 89.62,77.4 88.58,78.43 88.58,79.58 88.2,79.96 v2(88.2,80.2)
  BOTTOM w0.121: R526.1 90.72,76.3 89.62,77.4
AM335X_DDR_D6: length 8.2
  TOP w0.305: U2.P3 v2(89,79.4)
  BOTTOM w0.102: 90.12,77.4 89,78.52 v2(89,79.4)
  BOTTOM w0.121: 90.12,77.4 90.52,77.01 90.58,77.01 91.41,76.18 91.41,74.27 92.24,73.44 R527.1
AM335X_DDR_D7: length 10.1
  TOP w0.102: U2.P4 v2(89,80.2)
  BOTTOM w0.102: 90.63,77.4 89.42,78.61 89.42,79.82 89.04,80.2 v2(89,80.2)
  BOTTOM w0.121: 90.63,77.4 90.78,77.25 91.35,77.25 91.86,76.75 91.86,74.33 R528.1
AM335X_DDR_D8: length 5.3
  TOP w0.102: U2.J1 84.6,77.62 84.59,77.61 84.59,77.53 84.56,77.5 84.56,77.13 84.62,77.07
  TOP w0.121: 84.62,77.07 84.62,76.05 85,75.67 R529.1
AM335X_DDR_D9: length 5.3
  TOP w0.102: U2.K1 85.4,77.96 85.7,77.66 85.7,77.06
  TOP w0.121: 85.7,77.06 85.7,73.89 85.95,73.63 R530.1
AM335X_DDR_D10: length 6.5
  TOP w0.102: U2.K2 85.41,79 85.83,78.59 85.83,77.82 85.96,77.69 85.96,77.28 85.96,77.26
  TOP w0.121: 85.96,77.26 85.96,76.61 86.34,76.23 86.34,73.82 86.91,73.25 R531.1
AM335X_DDR_D11: length 5.4
  TOP w0.102: v2(85.8,79.4) U2.K3
  BOTTOM w0.102: 84.81,76.81 85.31,76.81 85.44,76.94 85.44,77.27 85.57,77.4 85.64,77.4 85.76,77.53 85.76,79.36 v2(85.8,79.4)
  BOTTOM w0.121: R532.1 84.05,76.05 84.81,76.81
AM335X_DDR_D12: length 5.4
  TOP w0.102: U2.K4 v2(85.8,80.2)
  BOTTOM w0.102: 85.95,77.4 85.95,77.43 85.97,77.44 85.97,78.79 86.21,79.03 86.21,79.86 85.86,80.2 v2(85.8,80.2)
  BOTTOM w0.121: 85.95,77.4 R533.1
AM335X_DDR_D13: length 4.4
  TOP w0.102: v2(86.6,79.4) U2.L3
  BOTTOM w0.102: v2(86.6,79.4) 86.6,77.4
  BOTTOM w0.121: 86.6,77.4 86.6,75.97 R534.1
AM335X_DDR_D14: length 8.1
  TOP w0.102: U2.L4 v2(86.6,80.2)
  BOTTOM w0.102: 86.98,77.4 86.98,80.05 86.83,80.2 v2(86.6,80.2)
  BOTTOM w0.121: 86.98,77.4 86.98,76.49 87.11,76.36 87.28,76.36 87.41,76.24 87.41,73.95 R535.1
AM335X_DDR_D15: length 6.7
  TOP w0.102: 87,77.4 U2.M1
  TOP w0.121: R536.1 89.76,73.57 89.38,73.95 88.53,73.95 87.44,75.03 87.44,76.9 87,77.35 87,77.4
AM335X_DDR_DQM0: length 8.8
  TOP w0.102: 87.39,77.4 87.39,78.87 87.27,79 U2.M2
  TOP w0.121: R16.1 90.72,74.33 90.46,74.59 88.43,74.59 87.79,75.22 87.79,75.26 87.79,75.86 87.79,75.9 87.79,77 87.39,77.4
AM335X_DDR_DQM1: length 3.9
  TOP w0.102: U2.J2 84.6,78.99 85,78.59 85,78.02 85.25,77.76 85.31,77.76 85.44,77.63 85.44,77.13 85.25,76.95
  TOP w0.121: 85.25,76.95 v1(85.25,76.3)
  BOTTOM w0.121: R19.1 85,76.05 v1(85.25,76.3)
AM335X_DDR_DQS0: length 11.4
  TOP w0.102: 88.6,77.91 U2.P1
  TOP w0.121: 88.6,77.91 88.9,77.61 89.38,77.61 89.85,77.15 90.31,77.15 90.66,76.8 92.04,76.8 92.24,76.59 92.24,74.23 92.37,74.1 94.63,74.1 94.75,73.98 94.75,73.27 94.63,73.14 93.59,73.14 R17.1
AM335X_DDR_DQS1: length 6.5
  TOP w0.102: 86.2,77.6 U2.L1
  TOP w0.121: R20.1 87.98,73.13 88.11,73.25 88.11,73.63 87.67,74.08 86.84,74.08 86.59,74.33 86.59,76.36 86.21,76.74 86.21,77.37 86.2,77.38 86.2,77.6
AM335X_DDR_DQSN0: length 11.3
  TOP w0.102: U2.P2 88.6,78.99 89.06,78.53 89.06,78.02 89.11,77.97
  TOP w0.121: 89.11,77.97 89.22,77.86 89.49,77.86 89.95,77.4 90.41,77.4 90.69,77.12 94.44,77.12 95.31,76.24 95.31,75.38 95.31,75.07 95.48,74.9 R539.1
AM335X_DDR_DQSN1: length 7.4
  TOP w0.102: 86.6,77.4 86.59,77.41 86.59,78.59 86.2,78.97 U2.L2
  TOP w0.121: R540.1 88.49,73.13 88.37,73.25 88.37,73.76 87.67,74.46 87.16,74.46 86.91,74.71 86.91,76.43 86.6,76.74 86.6,77.4
AM335X_DDR_RASN: length 6.4
  TOP w0.102: U2.G4 v2(82.6,80.2)
  BOTTOM w0.102: v2(82.6,80.2) 82.62,80.2 82.98,79.84 82.98,79.09 81.83,77.94 81.83,77.82 81.4,77.4
  BOTTOM w0.121: 81.4,77.4 80.24,76.24 R14.1
AM335X_DDR_WEN: length 10.5
  TOP w0.102: 78.77,77.4 79.38,78.01 79.38,78.87 79.25,79 U2.B2
  TOP w0.121: 78.77,77.4 78.37,77 75.48,77 74.44,75.96 74.44,73.74 R15.1
AM335X_DDRODT: length 5.8
  TOP w0.102: U2.G1 83,77.82 82.97,77.79 82.97,77.13 82.84,77 82.71,77
  TOP w0.121: R543.1 82.14,73.44 81.95,73.63 81.95,75.48 82.14,75.67 82.46,75.67 82.59,75.79 82.59,76.87 82.71,77
AM335X_ECAP0_IN_PWM0_OUT: length 46
  TOP w0.121: v1(79.56,97.07) 79.28,96.78 79.28,95.08 79.92,94.44 79.92,91.92 U2.C18 ; v1(76.16,132.68) 74.43,132.68 74.1,133.01 R255.2
  BOTTOM w0.121: v1(79.56,97.07) 79.56,98.39 79.46,98.49 79.46,100.87 79.74,101.15 79.74,102.96 79.08,103.62 79.08,106.83 78.39,107.51 78.39,118.92 76.42,120.88 76.42,123.53 75.81,124.14 75.81,129.17 76.16,129.53 v1(76.16,132.68)
AM335X_EXT_WAKEUP: length 114.8
  TOP w0.102: 77.1,80.56 77.6,80.56 77.89,80.27 78.34,80.27 78.53,80.46 78.53,80.6 78.93,81 79.4,81 U2.C5
  TOP w0.121: 77.1,80.56 76.36,80.56 75.48,79.67 71.79,79.67 71.4,79.28 71.05,79.28 70.68,78.91 68.9,78.91 68.68,78.68 68.68,78.59 68.54,78.46 68.54,75.48 67.75,74.69 v1(67.17,74.69) ; v1(75.63,144.69) 74.36,145.96 67.08,145.96 v1(65.94,147.1)
  BOTTOM w0.121: v1(67.17,74.69) 67.17,78.07 64.81,80.43 64.81,82.08 64.43,82.46 64.43,83.22 63.72,83.92 63.72,87.35 63.03,88.05 63.03,92.62 63.09,92.68 63.09,97.76 63.41,98.08 64.05,98.08 64.6,98.64 64.6,100.97 64.35,101.22 64.35,112.13 59.85,116.62 59.85,120.56 58.39,122.02 58.39,129.64 57.95,130.09 57.95,134.91 57.31,135.55 57.31,140.37 57.7,140.75 59.47,140.75 61.76,143.04 61.76,145.2 63.66,147.1 v1(65.94,147.1) ; v1(75.63,144.69) 76.11,144.21 R207.2
AM335X_EXTINTN: length 121
  TOP w0.102: U2.B18 79,91.98 79.18,92.16 79.18,92.21 v2(79.23,92.26)
  LY3 w0.102: 77.58,92.9 77.58,92.77 77.99,92.37 79.13,92.37 v2(79.23,92.26)
  LY3 w0.133: v1(13.45,94.93) 14.44,94.93 14.82,94.55 21.65,94.55 21.82,94.72 41.14,94.72 43.46,92.4 59.51,92.4 60.34,93.23 69.66,93.23 71.43,95 76.86,95 77.58,94.27 77.58,92.9
  BOTTOM w0.121: v1(13.45,94.93) 13.45,65.7 6.9,59.14 6.9,47.28
AM335X_GPMC_A0: length 79.9
  TOP w0.102: v2(89.8,88.2) U2.R13
  TOP w0.121: R193.2 90.16,122.92 94.14,122.92 95.45,124.22 v1(96.3,124.22)
  LY4 w0.102: v2(89.8,88.2) 90.22,88.62 91.06,88.62
  LY4 w0.133: v1(96.3,124.22) 96.33,124.25 96.33,128.99 96.46,129.12 97.17,129.12 97.29,128.99 97.29,125.72 97.42,125.59 97.9,125.59 98.03,125.72 98.03,128.92 98.16,129.04 98.84,129.04 98.97,128.92 98.97,125.46 99.1,125.34 99.86,125.34 99.99,125.46 99.99,127.6 100.11,127.72 100.94,127.72 101.07,127.6 101.07,120.15 101.78,119.43 101.78,118.19 100.69,117.1 100.69,101.61 99.79,100.7 99.79,94.31 99.22,93.74 99.22,92.9 97.86,91.55 97.02,91.55 96.64,91.55 95.77,90.68 95.77,89.06 95.28,88.56 91.12,88.56 91.06,88.62
AM335X_GPMC_A1: length 80.5
  TOP w0.102: U2.V14 94.29,88.6 94.96,89.27 v1(94.98,89.27)
  TOP w0.121: v1(96.4,123.33) 95.69,123.33 95.07,122.71 95.05,122.71 94.92,122.58 91.04,122.58 88.54,120.08 85.36,120.08 R574.2
  LY4 w0.133: v1(94.98,89.27) 94.98,89.29 94.62,89.66 94.62,91.65 95.3,92.33 96.12,92.33 96.25,92.45 96.25,93.51 96.37,93.64 96.76,93.64 96.89,93.51 96.89,92.45 97.01,92.33 97.29,92.33 98.39,93.42 98.39,98.77 98.26,98.89 96.46,98.89 96.33,99.02 96.33,103.54 96.46,103.67 96.99,103.67 97.12,103.54 97.12,99.78 97.24,99.66 97.65,99.66 97.78,99.78 97.78,114.01 97.65,114.13 97.29,114.13 97.17,114.01 97.17,112.28 97.04,112.15 96.64,112.15 96.52,112.28 96.52,114.15 95.93,114.74 95.93,117.45 96.06,117.57 98.26,117.57 98.39,117.7 98.39,119.67 98.26,119.8 96.06,119.8 95.93,119.93 95.93,120.36 96.06,120.48 97.85,120.48 97.98,120.61 97.98,120.97 97.85,121.09 96.06,121.09 95.93,121.22 95.93,123.2 96.06,123.33 v1(96.4,123.33)
AM335X_GPMC_A2: length 80.4
  TOP w0.102: 93,89 91.4,89 U2.U14
  TOP w0.121: R575.2 83.45,120.31 83.96,119.79 88.61,119.79 91.15,122.33 96.12,122.33 v1(96.38,122.59) ; v1(95.06,90.05) 94.92,89.91 94.92,89.84 94.07,89 93,89
  LY4 w0.133: v1(96.38,122.59) 96.38,121.55 96.5,121.42 99.15,121.42 99.28,121.3 99.28,117.44 99.15,117.31 96.4,117.31 96.28,117.18 96.28,115 96.4,114.87 97.09,114.87 97.22,115 97.22,116.45 97.34,116.57 99.41,116.57 99.54,116.45 99.54,109.41 99.41,109.28 98.92,109.28 98.79,109.41 98.79,115.35 98.67,115.48 98.18,115.48 98.06,115.35 98.06,99.28 98.18,99.15 98.52,99.15 98.65,99.03 98.65,93.31 97.4,92.07 96.23,92.07 95.06,90.9 v1(95.06,90.05)
AM335X_GPMC_A3: length 79.5
  TOP w0.102: v2(90.6,89) U2.T14
  TOP w0.121: R576.2 81.01,120.31 81.77,119.54 88.71,119.54 91.25,122.08 96.66,122.08 v1(97.14,122.57)
  LY4 w0.102: 93,88.82 91.48,88.82 91.3,89 v2(90.6,89)
  LY4 w0.133: 93,88.82 93,88.82 95.17,88.82 95.51,89.16 95.51,90.86 96.46,91.81 97.54,91.81 98.96,93.22 98.96,99.3 98.83,99.43 98.44,99.43 98.32,99.55 98.32,108.85 98.44,108.98 98.92,108.98 99.05,108.85 99.05,101.76 99.17,101.64 99.59,101.64 99.72,101.76 99.72,108.85 99.84,108.98 100.31,108.98 100.43,109.1 100.43,111.95 100.31,112.08 99.93,112.08 99.8,112.2 99.8,116.92 99.67,117.05 99.67,117.05 99.54,117.18 99.54,122.44 99.41,122.57 v1(97.14,122.57)
AM335X_GPMC_A4: length 48.7
  TOP w0.102: v2(89.8,89) U2.R14
  TOP w0.121: R206.2 v1(92.24,111.11)
  LY4 w0.102: v2(89.8,89) 89.84,89 90.26,89.42 91.48,89.42 91.78,89.11 93,89.11 ; 91.3,92.65 91.3,91.87 91.43,91.74 92.11,91.74 92.24,91.62 92.24,89.75 92.37,89.62 93,89.62
  LY4 w0.133: 93,89.11 93.79,89.11 93.92,89.24 93.92,89.47 93.76,89.62 93,89.62 ; 91.3,92.65 91.43,92.77 92.04,92.77 92.17,92.9 92.17,93.87 92.04,94 91.22,94 91.09,94.12 91.09,94.86 91.22,94.99 94,94.99 94.13,95.12 94.13,95.98 94,96.11 91.22,96.11 91.1,96.24 91.1,96.89 91.22,97.01 93.9,97.01 94.02,97.14 94.02,98.03 93.9,98.16 91.68,98.16 91.55,98.28 91.55,98.71 91.68,98.84 92.91,98.84 93.04,98.96 93.04,99.89 92.91,100.02 91.68,100.02 91.55,100.14 91.55,100.52 91.68,100.65 92.91,100.65 93.04,100.77 93.04,101.23 93.05,101.25 93.05,102.73 92.08,103.7 92.08,104.17 92.21,104.3 92.99,104.3 93.13,104.44 93.13,104.7 92.99,104.84 92.21,104.84 92.08,104.97 92.08,110.51 92.24,110.66 v1(92.24,111.11)
AM335X_GPMC_A5: length 46.8
  TOP w0.102: U2.V15 93,89.4
  TOP w0.121: 93,89.4 94.07,89.4 94.47,89.8 94.47,90.51 v1(94.09,90.89) ; R209.2 90.97,111.75 91.5,111.21 v1(91.5,111.06)
  LY3 w0.133: v1(93.48,100.85) 93.48,102.72 93.36,102.85 92.54,102.85 91.6,103.79 91.42,103.79 89.74,102.11 89.55,102.11 89.36,102.3 89.36,102.49 91.04,104.17 91.04,104.36 90.85,104.54 90.66,104.54 88.99,102.87 88.8,102.87 88.61,103.06 88.61,103.25 90.28,104.92 90.28,105.11 90.1,105.3 89.91,105.3 88.23,103.62 88.04,103.62 87.85,103.81 87.85,104 89.53,105.68 89.53,105.86 89.03,106.36 89.03,106.55 90.64,108.16 90.64,109.89 91.5,110.75 v1(91.5,111.06)
  LY4 w0.102: 93,91.12 92.43,91.7 92.43,92.9
  LY4 w0.133: v1(93.48,100.85) 94.28,100.05 94.28,97.23 94.39,97.12 94.39,94.86 94.26,94.73 92.55,94.73 92.43,94.6 92.43,92.9 ; v1(94.09,90.89) 93.23,90.89 93,91.12
AM335X_GPMC_A6: length 47.2
  TOP w0.102: U2.U15 91,89.41 91.46,89.87 92.01,89.87 92.11,89.97
  TOP w0.121: v1(93.71,111.14) 93.38,111.47 R214.2 ; v1(95.8,93.52) 96.31,93 96.31,92.09 95.56,91.33 93.51,91.33 92.15,89.97 92.11,89.97
  LY3 w0.133: v1(93.71,111.14) 94.35,111.14 94.47,111.01 94.47,105.24 95.03,104.69 95.03,99.63 96.02,98.64 96.68,98.64 96.81,98.77 96.81,99.65 96.68,99.79 95.95,99.79 95.82,99.92 95.82,100.19 95.95,100.32 96.68,100.32 96.81,100.45 96.81,100.72 96.68,100.85 95.95,100.85 95.82,100.99 95.82,101.25 95.95,101.39 96.68,101.39 96.81,101.52 96.81,101.79 96.68,101.92 95.95,101.92 95.82,102.05 95.82,102.32 95.95,102.45 96.68,102.45 96.81,102.59 96.81,104.71 96.94,104.84 97.42,104.84 97.55,104.71 v1(97.55,98.39)
  LY4 w0.133: v1(95.8,93.52) 95.8,94.39 95.95,94.54 95.95,94.71 96.76,95.52 96.76,97.6 v1(97.55,98.39)
AM335X_GPMC_A7: length 42.7
  TOP w0.102: v2(90.6,89.8) U2.T15
  TOP w0.121: R217.2 88.12,110.17 v1(91.55,110.17)
  LY4 w0.102: 91,92.9 91,90.41 91.13,90.28 91.43,90.28 91.55,90.41 91.55,91.41 91.68,91.54 91.91,91.54 92.04,91.41 92.04,89.93 91.91,89.8 v2(90.6,89.8)
  LY4 w0.133: 91,92.9 91,92.95 91.13,93.08 91.78,93.08 91.91,93.2 91.91,93.61 91.78,93.74 90.96,93.74 90.83,93.86 90.83,95.12 90.96,95.25 93.74,95.25 93.87,95.38 93.87,95.72 93.74,95.85 90.96,95.85 90.83,95.98 90.83,97.15 90.96,97.27 92.04,97.27 92.16,97.4 92.16,97.77 92.04,97.9 91.42,97.9 91.29,98.02 91.29,98.97 91.55,99.23 91.55,99.62 91.29,99.88 91.29,100.78 91.42,100.91 92.65,100.91 92.78,101.03 92.78,101.84 91.55,103.06 v1(91.55,110.17)
AM335X_GPMC_A8: length 32
  TOP w0.102: 93,91.17 92.04,90.21 91.81,90.21 U2.V16
  TOP w0.121: R511.2 89.96,110.62 91.93,110.62 92.15,110.4 v1(93.79,110.4) ; 93,91.17 93.41,91.58 94.91,91.58 95.36,92.03 95.36,93.7 95.85,94.19 96.28,94.19 v1(96.51,94.42)
  LY3 w0.133: v1(93.79,110.4) 93.79,109.45 93.93,109.31 93.93,100.02 96.61,97.34 v1(97.93,97.34)
  LY4 w0.133: v1(97.93,97.34) 97.4,96.81 97.4,95.31 v1(96.51,94.42)
AM335X_GPMC_A9: length 80.3
  TOP w0.102: U2.U16 91.03,90.2 91.41,90.59 92.07,90.59 93.31,91.83
  TOP w0.121: v1(95.51,94.73) 95.51,94.31 95.11,93.92 95.11,92.87 94.06,91.83 93.31,91.83
  LY3 w0.133: v1(58.84,131.23) 82.94,131.23 83.63,130.54 89.67,130.54 90.41,131.28 v1(92.21,131.28)
  LY4 w0.133: v1(92.21,131.28) 95.36,128.13 95.36,114.57 96,113.93 96,111.84 95.61,111.46 95.61,95.8 95.51,95.69 v1(95.51,94.73)
  BOTTOM w0.121: R512.2 v1(58.84,131.23)
AM335X_GPMC_A10: length 44.5
  TOP w0.102: v2(90.6,90.6) U2.T16
  TOP w0.121: R230.2 91.07,133.48 v1(91.07,132.78)
  LY4 w0.102: v2(90.6,90.6) 90.6,91.46 90.61,91.47 90.61,92.87
  LY4 w0.133: v1(91.07,132.78) 90.13,131.84 90.13,113.5 90.4,113.23 90.4,106.89 90.39,106.89 90.39,102.44 90.99,101.84 90.99,98.06 90.57,97.63 90.57,92.9 90.61,92.87
AM335X_GPMC_A11: length 82.6
  TOP w0.102: v2(92.93,91.99) 91.94,91 U2.V17
  LY3 w0.133: v1(56.63,122.08) 65.31,122.08 65.44,121.95 65.44,120.44 65.57,120.31 65.84,120.31 65.97,120.44 65.97,121.95 66.11,122.08 66.37,122.08 66.51,121.95 66.51,120.44 66.64,120.31 66.91,120.31 67.04,120.44 67.04,121.95 67.17,122.08 67.44,122.08 67.57,121.95 67.57,120.44 67.71,120.31 67.97,120.31 68.11,120.44 68.11,121.95 68.24,122.08 70.98,122.08 71.68,121.39 71.68,120.57 71.96,120.29 72.77,120.29 72.79,120.28 76.64,120.28 77.3,120.94 82.87,120.94 83.12,121.2 88.02,121.2 88.15,121.07 88.15,119.32 88.28,119.19 91.55,119.19 91.68,119.06 91.68,117.59 92.09,117.18 92.9,117.18 v1(92.95,117.14)
  LY4 w0.102: v2(92.93,91.99) 92.93,91.99
  LY4 w0.133: 92.93,91.99 94.32,91.99 95.24,92.9 95.24,94.27 95.06,94.45 95.06,95.69 95.35,95.99 95.35,97.79 94.6,98.54 94.6,101.92 95.35,102.67 95.35,111.57 95.73,111.95 95.73,113.81 92.95,116.6 v1(92.95,117.14)
  BOTTOM w0.121: v1(56.63,122.08) 56.12,122.59 R233.2
AM335X_GPMC_AD0: length 70.2
  TOP w0.102: U2.U7 91,83 91.41,83.41 92.07,83.41
  TOP w0.121: 92.07,83.41 92.48,83 95.48,83 95.82,83.35 95.82,84.53 96.23,84.93 96.28,84.93 v1(96.48,85.14) ; R140.2 v1(139.61,106.26)
  BOTTOM w0.121: v1(96.48,85.14) 96.48,85.37 96.75,85.64 96.75,85.7 97.08,86.03 97.65,86.03 97.78,86.16 98.94,86.16 99.14,85.96 111.4,85.96 114.86,89.41 128.81,89.41 129.57,90.18 131.56,90.18 132.16,89.58 137.09,89.58 138.05,90.54 138.05,92.04 137.88,92.21 137.88,98.48 137.26,99.1 137.26,100.57 139.34,102.66 139.34,103.84 140.05,104.55 140.05,105.82 v1(139.61,106.26)
AM335X_GPMC_AD1: length 71
  TOP w0.102: 92.16,83 U2.V7
  TOP w0.121: 92.16,83 92.4,82.76 95.58,82.76 96.07,83.24 96.07,84.43 96.33,84.69 96.79,84.69 v1(97.25,85.14) ; R141.2 v1(139.61,107.66)
  BOTTOM w0.121: v1(97.25,85.14) 97.25,85.44 97.59,85.78 97.75,85.78 97.88,85.91 98.84,85.91 99.04,85.71 111.5,85.71 114.96,89.17 121.17,89.17 128.91,89.17 129.67,89.93 131.4,89.93 131.99,89.34 137.19,89.34 138.3,90.44 138.3,92.29 138.13,92.46 138.13,98.66 137.56,99.22 137.56,100.53 139.59,102.55 139.59,103.74 140.3,104.45 140.3,106.97 v1(139.61,107.66)
AM335X_GPMC_AD2: length 77.5
  TOP w0.102: v2(89.8,83.4) U2.R8
  TOP w0.121: R142.2 140.12,109.77 v1(139.61,110.27) ; v1(105.83,87.67) 105.83,87.98 106.91,89.06 116.76,89.06 117.17,89.47 128.96,89.47 129.84,90.36 131.6,90.36 132.56,89.4 137.68,89.4 138.11,89.84 138.74,90.46 v1(140.01,90.46)
  LY3 w0.133: v1(105.83,87.67) 105.57,87.67 101.89,83.98 97.57,83.98 96.57,82.98 93.6,82.98 92.78,83.8 90.2,83.8 v2(89.8,83.4)
  BOTTOM w0.121: v1(140.01,90.46) 139.78,90.69 139.78,94.37 140.3,94.88 140.3,97.88 139.51,98.67 139.51,101.77 140.55,102.81 140.55,108.83 140.12,109.26 140.12,109.77 v1(139.61,110.27)
AM335X_GPMC_AD3: length 78.5
  TOP w0.102: v2(90.6,83.4) U2.T8
  TOP w0.121: v1(140.63,90.69) 140.42,90.9 138.83,90.9 137.57,89.65 132.66,89.65 131.7,90.61 129.74,90.61 128.85,89.72 116.95,89.72 116.54,89.32 106.53,89.32 v1(105.89,88.68) ; R143.2 140.6,110.43 v1(140.6,110.27)
  LY3 w0.133: v1(105.89,88.68) 106.27,88.31 106.27,88.11 106.46,87.92 106.46,87.57 102.62,83.72 98.58,83.72 97.95,83.1 97.95,83.1 97.57,82.72 93.29,82.72 92.44,83.57 90.77,83.57 v2(90.6,83.4)
  BOTTOM w0.121: v1(140.63,90.69) 140.52,90.69 140.03,91.18 140.03,94.26 140.55,94.78 140.55,97.99 139.76,98.78 139.76,101.67 140.79,102.71 140.79,109.14 140.6,109.33 v1(140.6,110.27)
AM335X_GPMC_AD4: length 79.6
  TOP w0.102: U2.U8 91,83.82 91.41,84.24 92.12,84.24
  TOP w0.121: R144.2 v1(139.61,111.59) ; v1(140.5,91.48) 139.05,91.48 137.47,89.9 132.76,89.9 131.8,90.85 129.64,90.85 128.75,89.97 124.74,89.97 123.23,91.48 117.61,91.48 115.74,89.61 105.64,89.61 104.48,88.45 v1(104.48,87.21) ; v1(95.24,83.48) 94.94,83.78 94.94,84.09 94.68,84.35 92.23,84.35 92.12,84.24
  LY3 w0.133: v1(104.48,87.21) 101.52,84.24 97.47,84.24 97.46,84.24 97.4,84.24 96.4,83.24 95.48,83.24 v1(95.24,83.48)
  BOTTOM w0.121: v1(139.61,111.59) 140.61,111.59 141.04,111.16 141.04,102.54 140.11,101.61 140.11,98.77 140.79,98.09 140.79,94.68 140.28,94.16 140.28,91.7 v1(140.5,91.48)
AM335X_GPMC_AD5: length 79.2
  TOP w0.102: 93,83.8 U2.V8
  TOP w0.121: R145.2 v1(139.61,112.99) ; v1(94.49,83.91) 94.38,83.8 93,83.8 ; v1(103.72,87.18) 103.72,88.94 104.64,89.86 115.64,89.86 117.52,91.74 123.34,91.74 124.87,90.22 128.65,90.22 129.54,91.1 131.9,91.1 132.86,90.14 137.37,90.14 139.21,91.99 140.5,91.99 140.75,92.24 v1(140.75,92.23)
  LY3 w0.133: v1(103.72,87.18) 103.72,86.93 101.32,84.53 98.63,84.53 98.62,84.52 98.25,84.52 98.08,84.69 95.03,84.69 94.63,84.29 94.63,84.04 v1(94.49,83.91)
  BOTTOM w0.121: v1(139.61,112.99) 141.29,111.31 141.29,102.44 140.36,101.51 140.36,98.87 141.04,98.19 141.04,94.57 140.53,94.06 140.53,92.46 v1(140.75,92.23)
AM335X_GPMC_AD6: length 73.9
  TOP w0.102: v2(89.8,84.2) U2.R9
  TOP w0.121: v1(138.34,103.16) 132.61,103.16 129.8,100.36 114.02,100.36 112.51,98.84 103.45,98.84 102.12,97.51 100.69,97.51 v1(100.49,97.32) ; R146.2 v1(139.61,114.39)
  LY4 w0.133: v1(100.49,97.32) 100.49,94.09 99.74,93.34 99.74,91.32 98.75,90.32 98.45,90.32 97.57,89.45 97.57,89.15 95.21,86.79 93.83,86.79 93.47,86.43 91.36,86.43 90.94,86.01 90.18,86.01 89.59,85.42 89.59,85.4 89.38,85.19 89.38,84.72 89.63,84.46 89.63,84.37 v2(89.8,84.2)
  BOTTOM w0.121: v1(138.34,103.16) 138.6,103.42 138.6,104.75 138.92,105.07 138.92,113.7 v1(139.61,114.39)
